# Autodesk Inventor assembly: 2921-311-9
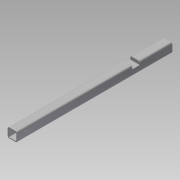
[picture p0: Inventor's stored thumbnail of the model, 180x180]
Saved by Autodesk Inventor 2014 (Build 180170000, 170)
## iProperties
Company: NHTSA/VRTC
Created: 2012-02
Part Number: 2921-311-9
Document SubType Name: Assembly
Designer: Mike Vanvoorhis
Project: CHILD SIDE IMPACT SLED
Description: BENCH FRAME TUBE #9 ASS'Y.
Mass: 2024.13 g
Surface Area: 1666.42 cm^2
Volume: 257.85 cm^3
Density: 7.85 g/cm^3
Title: BENCH FRAME TUBE #9 ASS'Y.
Subject: Child Side Impact Sled
Author: Dave Walker
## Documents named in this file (4)
- B:\VRTC_DWG\BIO\Non-P572\Child Side-Frontal Impact Sled\Side Impact Sled\Bench_Frame_Tube-9_Assembly.iam
- B:\VRTC_DWG\BIO\Non-P572\Child Side-Frontal Impact Sled\Side Impact Sled\2921-200-8 Tube.ipt
- B:\VRTC_DWG\BIO\Non-P572\Child Side-Frontal Impact Sled\Side Impact Sled\Bench_Frame_Tube-8_Cap_1.ipt
- B:\VRTC_DWG\BIO\Non-P572\Child Side-Frontal Impact Sled\Side Impact Sled\Bench_Frame_Tube-8_Cap_2.ipt
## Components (4 placed, 3 different names)
1. 2921-200-8 Tube:1 — Flush:1, Mate:5, Mate:6, Mate:10, Flush:4, Mate:11, Flush:5
2. Bench_Frame_Tube-8_Cap_1:1 — Flush:1, Mate:5, Mate:6, Mate:9, Mate:12
3. Bench_Frame_Tube-8_Cap_2:2 — Mate:9, Mate:10, Flush:4
4. Bench_Frame_Tube-8_Cap_2:3 — Mate:11, Mate:12, Flush:5
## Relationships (9: Mate 6, Flush 3)
- Flush:1: 2921-200-8 Tube:1 ↔ Bench_Frame_Tube-8_Cap_1:1
- Mate:5: 2921-200-8 Tube:1 ↔ Bench_Frame_Tube-8_Cap_1:1
- Mate:6: 2921-200-8 Tube:1 ↔ Bench_Frame_Tube-8_Cap_1:1
- Mate:9: Bench_Frame_Tube-8_Cap_1:1 ↔ Bench_Frame_Tube-8_Cap_2:2
- Mate:10: 2921-200-8 Tube:1 ↔ Bench_Frame_Tube-8_Cap_2:2
- Flush:4: 2921-200-8 Tube:1 ↔ Bench_Frame_Tube-8_Cap_2:2
- Mate:11: 2921-200-8 Tube:1 ↔ Bench_Frame_Tube-8_Cap_2:3
- Mate:12: Bench_Frame_Tube-8_Cap_1:1 ↔ Bench_Frame_Tube-8_Cap_2:3
- Flush:5: 2921-200-8 Tube:1 ↔ Bench_Frame_Tube-8_Cap_2:3
